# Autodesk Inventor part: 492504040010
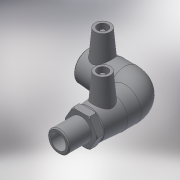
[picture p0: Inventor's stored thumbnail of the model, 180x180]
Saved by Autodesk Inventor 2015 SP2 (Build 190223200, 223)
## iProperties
Created: 2017-06
Part Number: 492504040010
Material: Generic
Description: PLASSON 90° ELBOW MALE TRANSITION 40-1"
Document SubType Name: Modeling
Designer: KIM
Mass: 195.96 g
Surface Area: 490.745 cm^2
Volume: 195.96 cm^3
Density: 1 g/cm^3
Appearance: Default
Author: KIM
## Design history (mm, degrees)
derived "492504.ipt"
feature "Solid1::492504.ipt"
tag "TaggingFeature1"
body "Solid1"
other parameters: "d2" = 56, "d4" = 30.66667, "d5" = 50.4, "d8" = 168 deg, "d10" = 17.6, "d11" = 5.86667, "d29" = 47, "d30" = 15, "d31" = 50.6, "d34" = 5 deg, "d41" = 4, "d42" = 14, "d43" = 0, "d48" = 64, "d50" = 34, "d51" = 17.6, "d52" = 44, "d54" = 90 deg, "d58" = 44, "d59" = 0, "d61" = 90 deg, "d86" = 3, "d87" = 0, "d93" = 0.1, "d94" = 8.5, "d95" = 33.249, "d96" = 23.2743, "d97" = 29, "d98" = 34, "d99" = 56, "d100" = 30.6, "d102" = 2, "d106" = 0, "L_" = 126, "L_1" = 44, "D_" = 29, "A_" = 47, "d_2" = 12, "L_2" = 34, "D_1" = 56, "R_" = 33.249
